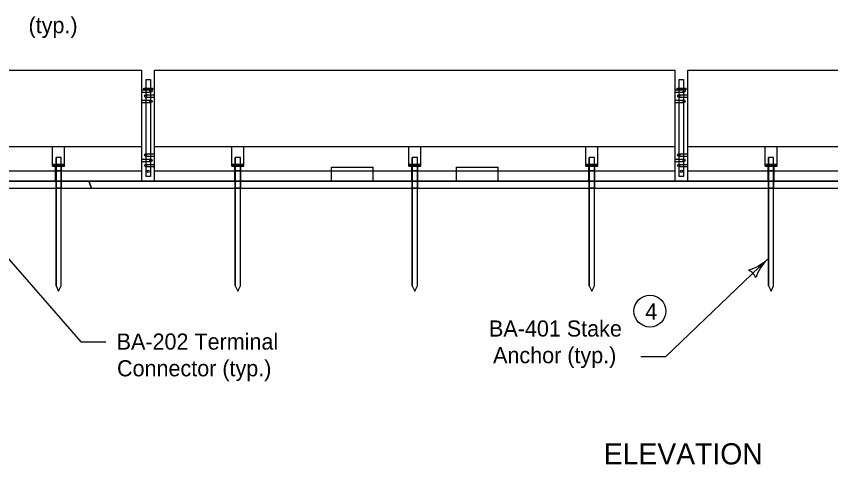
# Model space of a CAD drawing. Extents: x -2137026 to -2131464, y -2138478 to -2136524.
# Drawn here: x -2136307 to -2135538, y -2138383 to -2137959 of the extents above; entities that cross this region are included whole.
import ezdxf

# ---------------------------------------------------------------- set-up
doc = ezdxf.new("R2010")
doc.units = 0
for name, color, linetype in [('conPaving', 7, 'Continuous'), ('Level 2', 7, 'Continuous'), ('Level 3', 7, 'Continuous'), ('Level 41', 7, 'Continuous'), ('Level 9', 7, 'Continuous')]:
    doc.layers.add(name, color=color, linetype=linetype)

msp = doc.modelspace()

# ---------------------------------------------------------------- linework, layer by layer
at = {"layer": 'conPaving'}
for p, q in [((-2136269.98, -2138114.82), (-2136355.62, -2138114.82)), ((-2136269.6, -2138114.82), (-2136269.98, -2138114.82)), ((-2136269.6, -2138121.37), (-2136269.6, -2138114.82)), ((-2136264.69, -2138114.82), (-2136264.69, -2138121.37)), ((-2136188.75, -2138114.82), (-2136238.46, -2138114.82)), ((-2136238.46, -2138114.82), (-2136236.14, -2138121.37)), ((-2136236.14, -2138121.37), (-2136238.46, -2138114.82)), ((-2136176.38, -2138114.82), (-2136188.75, -2138114.82)), ((-2136100.81, -2138114.82), (-2136176.38, -2138114.82)), ((-2136100.44, -2138114.82), (-2136100.81, -2138114.82)), ((-2136100.44, -2138121.37), (-2136100.44, -2138114.82)), ((-2136095.52, -2138114.82), (-2136095.52, -2138121.37)), ((-2135970.18, -2138114.82), (-2136009.51, -2138114.82)), ((-2135933.32, -2138121.37), (-2135933.32, -2138114.82)), ((-2135928.41, -2138114.82), (-2135928.41, -2138121.37)), ((-2135766.2, -2138114.82), (-2135766.58, -2138114.82)), ((-2135766.2, -2138121.37), (-2135766.2, -2138114.82)), ((-2135760.92, -2138114.82), (-2135761.29, -2138114.82)), ((-2135761.29, -2138114.82), (-2135761.29, -2138121.37)), ((-2135685.35, -2138114.82), (-2135760.92, -2138114.82)), ((-2135597.04, -2138114.82), (-2135597.41, -2138114.82)), ((-2135597.04, -2138121.37), (-2135597.04, -2138114.82)), ((-2135592.12, -2138114.82), (-2135592.12, -2138121.37)), ((-2136431.8, -2138121.37), (-2136269.6, -2138121.37)), ((-2136264.69, -2138121.37), (-2136236.14, -2138121.37)), ((-2136236.14, -2138121.37), (-2136100.44, -2138121.37)), ((-2136095.52, -2138121.37), (-2135933.32, -2138121.37)), ((-2135928.41, -2138121.37), (-2135766.2, -2138121.37)), ((-2135761.29, -2138121.37), (-2135597.04, -2138121.37)), ((-2135592.12, -2138121.37), (-2135530.9, -2138121.37))]:
    msp.add_line(p, q, dxfattribs=at)
for points in [[(-2136238.46, -2138114.82), (-2136264.31, -2138114.82), (-2136264.69, -2138114.82)], [(-2136009.51, -2138114.82), (-2136095.15, -2138114.82), (-2136095.52, -2138114.82)], [(-2135933.32, -2138114.82), (-2135933.69, -2138114.82), (-2135970.18, -2138114.82)], [(-2135766.58, -2138114.82), (-2135852.22, -2138114.82), (-2135891.54, -2138114.82), (-2135928.03, -2138114.82), (-2135928.41, -2138114.82)], [(-2135597.41, -2138114.82), (-2135672.98, -2138114.82), (-2135685.35, -2138114.82)], [(-2135430.3, -2138114.82), (-2135466.79, -2138114.82), (-2135506.11, -2138114.82), (-2135591.75, -2138114.82), (-2135592.12, -2138114.82)]]:
    msp.add_lwpolyline(points, dxfattribs=at)
at = {"layer": 'Level 2'}
for p, q in [((-2136680.02, -2138009.96), (-2136188.5, -2138009.96)), ((-2136188.5, -2138114.57), (-2136188.5, -2138009.96)), ((-2136176.62, -2138114.57), (-2136176.62, -2138009.96)), ((-2136176.62, -2138009.96), (-2135685.1, -2138009.96)), ((-2135685.1, -2138114.57), (-2135685.1, -2138009.96)), ((-2135673.22, -2138114.57), (-2135673.22, -2138009.96)), ((-2135673.22, -2138009.96), (-2135181.7, -2138009.96)), ((-2136410.46, -2138078.28), (-2136246.26, -2138266.62)), ((-2136680.02, -2138082.05), (-2136188.5, -2138082.05)), ((-2136176.62, -2138082.05), (-2135685.1, -2138082.05)), ((-2135673.22, -2138082.05), (-2135181.7, -2138082.05)), ((-2136009.51, -2138101.71), (-2135970.18, -2138101.71)), ((-2135891.54, -2138101.71), (-2135852.22, -2138101.71)), ((-2136680.02, -2138104.99), (-2136188.5, -2138104.99)), ((-2136176.62, -2138104.99), (-2135685.1, -2138104.99)), ((-2136009.51, -2138114.82), (-2136009.51, -2138104.99)), ((-2135970.18, -2138114.82), (-2135970.18, -2138104.99)), ((-2135891.54, -2138114.82), (-2135891.54, -2138104.99)), ((-2135852.22, -2138114.82), (-2135852.22, -2138104.99)), ((-2135673.22, -2138104.99), (-2135181.7, -2138104.99)), ((-2136355.62, -2138114.82), (-2136188.75, -2138114.82)), ((-2136176.38, -2138114.82), (-2136009.51, -2138114.82)), ((-2135970.18, -2138114.82), (-2135891.54, -2138114.82)), ((-2135852.22, -2138114.82), (-2135685.35, -2138114.82)), ((-2135672.98, -2138114.82), (-2135506.11, -2138114.82)), ((-2135693.85, -2138280.43), (-2135598, -2138188.49)), ((-2136246.26, -2138266.62), (-2136222.65, -2138266.62)), ((-2135717.45, -2138280.43), (-2135693.85, -2138280.43))]:
    msp.add_line(p, q, dxfattribs=at)
msp.add_circle((-2135708.96, -2138237.57), 15, dxfattribs=at)
for centre, radius, start, end in [((-2135627.42, -2138157.82), 42.5, 285.73709, 313.80957), ((-2135568.58, -2138219.16), 42.5, 133.80957, 161.88206), ((-2135623.71, -2138213.16), 16.42, 26.07622, 61.54292)]:
    msp.add_arc(centre, radius, start, end, dxfattribs=at)
at = {"layer": 'Level 41'}
for p, q in [((-2136188.5, -2138028.56), (-2136180, -2138028.56)), ((-2136188.5, -2138030.68), (-2136180, -2138030.68)), ((-2136185.13, -2138033.48), (-2136176.62, -2138033.48)), ((-2135685.1, -2138028.56), (-2135676.6, -2138028.56)), ((-2135685.1, -2138030.68), (-2135676.6, -2138030.68)), ((-2135681.73, -2138033.48), (-2135673.22, -2138033.48)), ((-2136188.49, -2138038.39), (-2136180, -2138038.39)), ((-2136188.49, -2138040.51), (-2136180, -2138040.51)), ((-2136185.13, -2138035.6), (-2136176.62, -2138035.6)), ((-2135685.09, -2138038.39), (-2135676.6, -2138038.39)), ((-2135685.09, -2138040.51), (-2135676.6, -2138040.51)), ((-2135681.73, -2138035.6), (-2135673.22, -2138035.6)), ((-2136272.81, -2138100.62), (-2136272.81, -2138082.05)), ((-2136261.48, -2138100.62), (-2136261.48, -2138082.05)), ((-2136103.64, -2138100.62), (-2136103.64, -2138082.05)), ((-2136092.32, -2138100.62), (-2136092.32, -2138082.05)), ((-2135936.53, -2138100.62), (-2135936.53, -2138082.05)), ((-2135925.2, -2138100.62), (-2135925.2, -2138082.05)), ((-2135769.41, -2138100.62), (-2135769.41, -2138082.05)), ((-2135758.08, -2138100.62), (-2135758.08, -2138082.05)), ((-2135600.24, -2138100.62), (-2135600.24, -2138082.05)), ((-2135588.92, -2138100.62), (-2135588.92, -2138082.05)), ((-2136188.5, -2138094.1), (-2136180.01, -2138094.1)), ((-2136188.5, -2138096.22), (-2136180.01, -2138096.22)), ((-2136185.13, -2138089.18), (-2136176.63, -2138089.18)), ((-2136185.13, -2138091.31), (-2136176.63, -2138091.31)), ((-2135685.1, -2138094.1), (-2135676.61, -2138094.1)), ((-2135685.1, -2138096.22), (-2135676.61, -2138096.22)), ((-2135681.73, -2138089.18), (-2135673.23, -2138089.18)), ((-2135681.73, -2138091.31), (-2135673.23, -2138091.31)), ((-2136272.81, -2138100.62), (-2136261.48, -2138100.62)), ((-2136269.98, -2138114.82), (-2136269.98, -2138100.62)), ((-2136264.31, -2138114.82), (-2136264.31, -2138100.62)), ((-2136185.13, -2138099.01), (-2136176.63, -2138099.01)), ((-2136185.13, -2138101.14), (-2136176.63, -2138101.14)), ((-2136103.64, -2138100.62), (-2136092.32, -2138100.62)), ((-2136100.81, -2138114.82), (-2136100.81, -2138100.62)), ((-2136095.15, -2138114.82), (-2136095.15, -2138100.62)), ((-2135936.53, -2138100.62), (-2135925.2, -2138100.62)), ((-2135933.69, -2138114.82), (-2135933.69, -2138100.62)), ((-2135928.03, -2138114.82), (-2135928.03, -2138100.62)), ((-2135769.41, -2138100.62), (-2135758.08, -2138100.62)), ((-2135766.58, -2138114.82), (-2135766.58, -2138100.62)), ((-2135760.92, -2138114.82), (-2135760.92, -2138100.62)), ((-2135681.73, -2138099.01), (-2135673.23, -2138099.01)), ((-2135681.73, -2138101.14), (-2135673.23, -2138101.14)), ((-2135600.24, -2138100.62), (-2135588.92, -2138100.62)), ((-2135597.41, -2138114.82), (-2135597.41, -2138100.62)), ((-2135591.75, -2138114.82), (-2135591.75, -2138100.62))]:
    msp.add_line(p, q, dxfattribs=at)
for centre in [(-2136185.13, -2138034.54), (-2136180, -2138029.62), (-2135681.73, -2138034.54), (-2135676.6, -2138029.62), (-2136180, -2138039.45), (-2135676.6, -2138039.45), (-2136185.13, -2138090.24), (-2136180, -2138095.16), (-2135681.73, -2138090.24), (-2135676.6, -2138095.16), (-2136185.13, -2138100.07), (-2135681.73, -2138100.07)]:
    msp.add_circle(centre, 1.06, dxfattribs=at)
at = {"layer": 'Level 9'}
for p, q in [((-2136184.61, -2138018.73), (-2136180.51, -2138018.73)), ((-2136184.61, -2138026.92), (-2136184.61, -2138018.73)), ((-2136180.51, -2138018.73), (-2136180.51, -2138026.92)), ((-2135681.21, -2138018.73), (-2135677.12, -2138018.73)), ((-2135681.21, -2138026.92), (-2135681.21, -2138018.73)), ((-2135677.12, -2138018.73), (-2135677.12, -2138026.92)), ((-2136186.66, -2138026.92), (-2136178.47, -2138026.92)), ((-2136186.66, -2138028.56), (-2136186.66, -2138026.92)), ((-2136178.47, -2138026.92), (-2136178.47, -2138028.56)), ((-2135683.26, -2138026.92), (-2135675.07, -2138026.92)), ((-2135683.26, -2138028.56), (-2135683.26, -2138026.92)), ((-2135675.07, -2138026.92), (-2135675.07, -2138028.56)), ((-2136178.47, -2138028.56), (-2136186.66, -2138028.56)), ((-2136184.61, -2138110.48), (-2136184.61, -2138028.56)), ((-2136180.51, -2138028.56), (-2136180.51, -2138110.48)), ((-2135675.07, -2138028.56), (-2135683.26, -2138028.56)), ((-2135681.21, -2138110.48), (-2135681.21, -2138028.56)), ((-2135677.12, -2138028.56), (-2135677.12, -2138110.48)), ((-2136264.69, -2138092.42), (-2136269.6, -2138092.42)), ((-2136269.6, -2138092.42), (-2136269.6, -2138098.98)), ((-2136264.69, -2138092.42), (-2136269.6, -2138092.42)), ((-2136269.6, -2138213.67), (-2136269.6, -2138092.42)), ((-2136264.69, -2138098.98), (-2136264.69, -2138092.42)), ((-2136264.69, -2138213.67), (-2136264.69, -2138092.42)), ((-2136095.52, -2138092.42), (-2136100.44, -2138092.42)), ((-2136100.44, -2138092.42), (-2136100.44, -2138098.98)), ((-2136095.52, -2138092.42), (-2136100.44, -2138092.42)), ((-2136100.44, -2138213.67), (-2136100.44, -2138092.42)), ((-2136095.52, -2138098.98), (-2136095.52, -2138092.42)), ((-2136095.52, -2138213.67), (-2136095.52, -2138092.42)), ((-2135928.41, -2138092.42), (-2135933.32, -2138092.42)), ((-2135933.32, -2138092.42), (-2135933.32, -2138098.98)), ((-2135928.41, -2138092.42), (-2135933.32, -2138092.42)), ((-2135933.32, -2138213.67), (-2135933.32, -2138092.42)), ((-2135928.41, -2138098.98), (-2135928.41, -2138092.42)), ((-2135928.41, -2138213.67), (-2135928.41, -2138092.42)), ((-2135761.29, -2138092.42), (-2135766.2, -2138092.42)), ((-2135766.2, -2138092.42), (-2135766.2, -2138098.98)), ((-2135761.29, -2138092.42), (-2135766.2, -2138092.42)), ((-2135766.2, -2138213.67), (-2135766.2, -2138092.42)), ((-2135761.29, -2138098.98), (-2135761.29, -2138092.42)), ((-2135761.29, -2138213.67), (-2135761.29, -2138092.42)), ((-2135592.12, -2138092.42), (-2135597.04, -2138092.42)), ((-2135597.04, -2138092.42), (-2135597.04, -2138098.98)), ((-2135592.12, -2138092.42), (-2135597.04, -2138092.42)), ((-2135597.04, -2138213.67), (-2135597.04, -2138092.42)), ((-2135592.12, -2138098.98), (-2135592.12, -2138092.42)), ((-2135592.12, -2138213.67), (-2135592.12, -2138092.42)), ((-2136272.06, -2138098.98), (-2136272.06, -2138100.62)), ((-2136269.6, -2138098.98), (-2136272.06, -2138098.98)), ((-2136272.06, -2138100.62), (-2136272.06, -2138098.98)), ((-2136272.06, -2138100.62), (-2136269.98, -2138100.62)), ((-2136269.98, -2138100.62), (-2136269.6, -2138100.62)), ((-2136264.69, -2138098.98), (-2136269.6, -2138098.98)), ((-2136269.6, -2138098.98), (-2136269.6, -2138100.62)), ((-2136269.6, -2138100.62), (-2136269.6, -2138098.98)), ((-2136269.6, -2138098.98), (-2136264.69, -2138098.98)), ((-2136264.69, -2138100.62), (-2136269.6, -2138100.62)), ((-2136269.6, -2138100.62), (-2136269.6, -2138104.99)), ((-2136269.6, -2138100.62), (-2136264.69, -2138100.62)), ((-2136264.69, -2138100.62), (-2136264.69, -2138098.98)), ((-2136264.69, -2138098.98), (-2136264.69, -2138100.62)), ((-2136264.69, -2138104.99), (-2136264.69, -2138100.62)), ((-2136102.9, -2138098.98), (-2136102.9, -2138100.62)), ((-2136100.44, -2138098.98), (-2136102.9, -2138098.98)), ((-2136102.9, -2138100.62), (-2136102.9, -2138098.98)), ((-2136102.9, -2138100.62), (-2136100.81, -2138100.62)), ((-2136100.81, -2138100.62), (-2136100.44, -2138100.62)), ((-2136095.52, -2138098.98), (-2136100.44, -2138098.98)), ((-2136100.44, -2138098.98), (-2136100.44, -2138100.62)), ((-2136100.44, -2138100.62), (-2136100.44, -2138098.98)), ((-2136100.44, -2138098.98), (-2136095.52, -2138098.98)), ((-2136095.52, -2138100.62), (-2136100.44, -2138100.62)), ((-2136100.44, -2138100.62), (-2136100.44, -2138104.99)), ((-2136100.44, -2138100.62), (-2136095.52, -2138100.62)), ((-2136095.52, -2138100.62), (-2136095.52, -2138098.98)), ((-2136095.52, -2138098.98), (-2136095.52, -2138100.62)), ((-2136095.52, -2138104.99), (-2136095.52, -2138100.62)), ((-2136009.51, -2138104.99), (-2136009.51, -2138101.71)), ((-2135970.18, -2138104.99), (-2135970.18, -2138101.71)), ((-2135935.78, -2138098.98), (-2135935.78, -2138100.62)), ((-2135933.32, -2138098.98), (-2135935.78, -2138098.98)), ((-2135935.78, -2138100.62), (-2135935.78, -2138098.98)), ((-2135935.78, -2138100.62), (-2135933.69, -2138100.62)), ((-2135933.69, -2138100.62), (-2135933.32, -2138100.62)), ((-2135928.41, -2138098.98), (-2135933.32, -2138098.98)), ((-2135933.32, -2138098.98), (-2135933.32, -2138100.62)), ((-2135933.32, -2138100.62), (-2135933.32, -2138098.98)), ((-2135933.32, -2138098.98), (-2135928.41, -2138098.98)), ((-2135928.41, -2138100.62), (-2135933.32, -2138100.62)), ((-2135933.32, -2138100.62), (-2135933.32, -2138104.99)), ((-2135933.32, -2138100.62), (-2135928.41, -2138100.62)), ((-2135928.41, -2138100.62), (-2135928.41, -2138098.98)), ((-2135928.41, -2138098.98), (-2135928.41, -2138100.62)), ((-2135928.41, -2138104.99), (-2135928.41, -2138100.62)), ((-2135891.54, -2138104.99), (-2135891.54, -2138101.71)), ((-2135852.22, -2138104.99), (-2135852.22, -2138101.71)), ((-2135768.66, -2138098.98), (-2135768.66, -2138100.62)), ((-2135766.2, -2138098.98), (-2135768.66, -2138098.98)), ((-2135768.66, -2138100.62), (-2135768.66, -2138098.98)), ((-2135768.66, -2138100.62), (-2135766.58, -2138100.62)), ((-2135766.58, -2138100.62), (-2135766.2, -2138100.62)), ((-2135761.29, -2138098.98), (-2135766.2, -2138098.98)), ((-2135766.2, -2138098.98), (-2135766.2, -2138100.62)), ((-2135766.2, -2138100.62), (-2135766.2, -2138098.98)), ((-2135766.2, -2138098.98), (-2135761.29, -2138098.98)), ((-2135761.29, -2138100.62), (-2135766.2, -2138100.62)), ((-2135766.2, -2138100.62), (-2135766.2, -2138104.99)), ((-2135766.2, -2138100.62), (-2135761.29, -2138100.62)), ((-2135761.29, -2138100.62), (-2135761.29, -2138098.98)), ((-2135761.29, -2138098.98), (-2135761.29, -2138100.62)), ((-2135761.29, -2138104.99), (-2135761.29, -2138100.62)), ((-2135599.5, -2138098.98), (-2135599.5, -2138100.62)), ((-2135597.04, -2138098.98), (-2135599.5, -2138098.98)), ((-2135599.5, -2138100.62), (-2135599.5, -2138098.98)), ((-2135599.5, -2138100.62), (-2135597.41, -2138100.62)), ((-2135597.41, -2138100.62), (-2135597.04, -2138100.62)), ((-2135592.12, -2138098.98), (-2135597.04, -2138098.98)), ((-2135597.04, -2138098.98), (-2135597.04, -2138100.62)), ((-2135597.04, -2138100.62), (-2135597.04, -2138098.98)), ((-2135597.04, -2138098.98), (-2135592.12, -2138098.98)), ((-2135592.12, -2138100.62), (-2135597.04, -2138100.62)), ((-2135597.04, -2138100.62), (-2135597.04, -2138104.99)), ((-2135597.04, -2138100.62), (-2135592.12, -2138100.62)), ((-2135592.12, -2138100.62), (-2135592.12, -2138098.98)), ((-2135592.12, -2138098.98), (-2135592.12, -2138100.62)), ((-2135592.12, -2138104.99), (-2135592.12, -2138100.62)), ((-2136264.69, -2138104.99), (-2136269.6, -2138104.99)), ((-2136269.6, -2138104.99), (-2136269.6, -2138114.82)), ((-2136269.6, -2138104.99), (-2136264.69, -2138104.99)), ((-2136264.69, -2138114.82), (-2136264.69, -2138104.99)), ((-2136180.51, -2138110.48), (-2136184.61, -2138110.48)), ((-2136095.52, -2138104.99), (-2136100.44, -2138104.99)), ((-2136100.44, -2138104.99), (-2136100.44, -2138114.82)), ((-2136100.44, -2138104.99), (-2136095.52, -2138104.99)), ((-2136095.52, -2138114.82), (-2136095.52, -2138104.99)), ((-2136009.51, -2138104.99), (-2135970.18, -2138104.99)), ((-2135928.41, -2138104.99), (-2135933.32, -2138104.99)), ((-2135933.32, -2138104.99), (-2135933.32, -2138114.82)), ((-2135933.32, -2138104.99), (-2135928.41, -2138104.99)), ((-2135928.41, -2138114.82), (-2135928.41, -2138104.99)), ((-2135891.54, -2138104.99), (-2135852.22, -2138104.99)), ((-2135761.29, -2138104.99), (-2135766.2, -2138104.99)), ((-2135766.2, -2138104.99), (-2135766.2, -2138114.82)), ((-2135766.2, -2138104.99), (-2135761.29, -2138104.99)), ((-2135761.29, -2138114.82), (-2135761.29, -2138104.99)), ((-2135677.12, -2138110.48), (-2135681.21, -2138110.48)), ((-2135592.12, -2138104.99), (-2135597.04, -2138104.99)), ((-2135597.04, -2138104.99), (-2135597.04, -2138114.82)), ((-2135597.04, -2138104.99), (-2135592.12, -2138104.99)), ((-2135592.12, -2138114.82), (-2135592.12, -2138104.99)), ((-2136987.54, -2138114.82), (-2134196.38, -2138114.82)), ((-2136264.69, -2138114.82), (-2136269.6, -2138114.82)), ((-2136269.6, -2138114.82), (-2136269.6, -2138121.37)), ((-2136269.6, -2138114.82), (-2136264.69, -2138114.82)), ((-2136264.69, -2138121.37), (-2136264.69, -2138114.82)), ((-2136188.75, -2138114.82), (-2136188.5, -2138114.57)), ((-2136176.62, -2138114.57), (-2136176.38, -2138114.82)), ((-2136095.52, -2138114.82), (-2136100.44, -2138114.82)), ((-2136100.44, -2138114.82), (-2136100.44, -2138121.37)), ((-2136100.44, -2138114.82), (-2136095.52, -2138114.82)), ((-2136095.52, -2138121.37), (-2136095.52, -2138114.82)), ((-2135928.41, -2138114.82), (-2135933.32, -2138114.82)), ((-2135933.32, -2138114.82), (-2135933.32, -2138121.37)), ((-2135933.32, -2138114.82), (-2135928.41, -2138114.82)), ((-2135928.41, -2138121.37), (-2135928.41, -2138114.82)), ((-2135761.29, -2138114.82), (-2135766.2, -2138114.82)), ((-2135766.2, -2138114.82), (-2135766.2, -2138121.37)), ((-2135766.2, -2138114.82), (-2135761.29, -2138114.82)), ((-2135761.29, -2138121.37), (-2135761.29, -2138114.82)), ((-2135685.35, -2138114.82), (-2135685.1, -2138114.57)), ((-2135673.22, -2138114.57), (-2135672.98, -2138114.82)), ((-2135592.12, -2138114.82), (-2135597.04, -2138114.82)), ((-2135597.04, -2138114.82), (-2135597.04, -2138121.37)), ((-2135597.04, -2138114.82), (-2135592.12, -2138114.82)), ((-2135592.12, -2138121.37), (-2135592.12, -2138114.82)), ((-2136691.9, -2138121.37), (-2134672.37, -2138121.37)), ((-2136264.69, -2138121.37), (-2136269.6, -2138121.37)), ((-2136269.6, -2138121.37), (-2136269.6, -2138213.67)), ((-2136269.6, -2138121.37), (-2136264.69, -2138121.37)), ((-2136264.69, -2138213.67), (-2136264.69, -2138121.37)), ((-2136095.52, -2138121.37), (-2136100.44, -2138121.37)), ((-2136100.44, -2138121.37), (-2136100.44, -2138213.67)), ((-2136100.44, -2138121.37), (-2136095.52, -2138121.37)), ((-2136095.52, -2138213.67), (-2136095.52, -2138121.37)), ((-2135928.41, -2138121.37), (-2135933.32, -2138121.37)), ((-2135933.32, -2138121.37), (-2135933.32, -2138213.67)), ((-2135933.32, -2138121.37), (-2135928.41, -2138121.37)), ((-2135928.41, -2138213.67), (-2135928.41, -2138121.37)), ((-2135761.29, -2138121.37), (-2135766.2, -2138121.37)), ((-2135766.2, -2138121.37), (-2135766.2, -2138213.67)), ((-2135766.2, -2138121.37), (-2135761.29, -2138121.37)), ((-2135761.29, -2138213.67), (-2135761.29, -2138121.37)), ((-2135592.12, -2138121.37), (-2135597.04, -2138121.37)), ((-2135597.04, -2138121.37), (-2135597.04, -2138213.67)), ((-2135597.04, -2138121.37), (-2135592.12, -2138121.37)), ((-2135592.12, -2138213.67), (-2135592.12, -2138121.37)), ((-2136269.6, -2138213.67), (-2136267.14, -2138218.58)), ((-2136269.6, -2138213.67), (-2136267.14, -2138218.58)), ((-2136267.14, -2138218.58), (-2136264.69, -2138213.67)), ((-2136267.14, -2138218.58), (-2136264.69, -2138213.67)), ((-2136100.44, -2138213.67), (-2136097.98, -2138218.58)), ((-2136100.44, -2138213.67), (-2136097.98, -2138218.58)), ((-2136097.98, -2138218.58), (-2136095.52, -2138213.67)), ((-2136097.98, -2138218.58), (-2136095.52, -2138213.67)), ((-2135933.32, -2138213.67), (-2135930.86, -2138218.58)), ((-2135933.32, -2138213.67), (-2135930.86, -2138218.58)), ((-2135930.86, -2138218.58), (-2135928.41, -2138213.67)), ((-2135930.86, -2138218.58), (-2135928.41, -2138213.67)), ((-2135766.2, -2138213.67), (-2135763.75, -2138218.58)), ((-2135766.2, -2138213.67), (-2135763.75, -2138218.58)), ((-2135763.75, -2138218.58), (-2135761.29, -2138213.67)), ((-2135763.75, -2138218.58), (-2135761.29, -2138213.67)), ((-2135597.04, -2138213.67), (-2135594.58, -2138218.58)), ((-2135597.04, -2138213.67), (-2135594.58, -2138218.58)), ((-2135594.58, -2138218.58), (-2135592.12, -2138213.67)), ((-2135594.58, -2138218.58), (-2135592.12, -2138213.67))]:
    msp.add_line(p, q, dxfattribs=at)
for points in [[(-2136272.06, -2138098.98), (-2136262.23, -2138098.98), (-2136262.23, -2138100.62), (-2136272.06, -2138100.62)], [(-2136262.23, -2138100.62), (-2136262.23, -2138098.98), (-2136264.69, -2138098.98)], [(-2136264.69, -2138100.62), (-2136264.31, -2138100.62), (-2136262.23, -2138100.62)], [(-2136102.9, -2138098.98), (-2136093.06, -2138098.98), (-2136093.06, -2138100.62), (-2136102.9, -2138100.62)], [(-2136093.06, -2138100.62), (-2136093.06, -2138098.98), (-2136095.52, -2138098.98)], [(-2136095.52, -2138100.62), (-2136095.15, -2138100.62), (-2136093.06, -2138100.62)], [(-2135935.78, -2138098.98), (-2135925.95, -2138098.98), (-2135925.95, -2138100.62), (-2135935.78, -2138100.62)], [(-2135925.95, -2138100.62), (-2135925.95, -2138098.98), (-2135928.41, -2138098.98)], [(-2135928.41, -2138100.62), (-2135928.03, -2138100.62), (-2135925.95, -2138100.62)], [(-2135768.66, -2138098.98), (-2135758.83, -2138098.98), (-2135758.83, -2138100.62), (-2135768.66, -2138100.62)], [(-2135758.83, -2138100.62), (-2135758.83, -2138098.98), (-2135761.29, -2138098.98)], [(-2135761.29, -2138100.62), (-2135760.92, -2138100.62), (-2135758.83, -2138100.62)], [(-2135599.5, -2138098.98), (-2135589.67, -2138098.98), (-2135589.67, -2138100.62), (-2135599.5, -2138100.62)], [(-2135589.67, -2138100.62), (-2135589.67, -2138098.98), (-2135592.12, -2138098.98)], [(-2135592.12, -2138100.62), (-2135591.75, -2138100.62), (-2135589.67, -2138100.62)]]:
    msp.add_lwpolyline(points, dxfattribs=at)
for centre in [(-2136182.56, -2138105.57), (-2135679.16, -2138105.57)]:
    msp.add_circle(centre, 1.02, dxfattribs=at)

# ---------------------------------------------------------------- texts
at = {"layer": 'Level 2'}
msp.add_text('4', height=15.2, dxfattribs=at).set_placement((-2135713.33, -2138245.48))
at = {"layer": 'Level 3'}
for s, height, p in [('(typ.)', 15.2, (-2136295.52, -2137975.2)), ('BA-401 Stake', 15.2, (-2135860.81, -2138261.57)), ('BA-202 Terminal', 15.2, (-2136212.34, -2138273.92)), ('Anchor (typ.)', 15.2, (-2135856.98, -2138286.77)), ('Connector (typ.)', 15.2, (-2136212, -2138299.12)), ('ELEVATION', 20, (-2135752.5, -2138382.29))]:
    msp.add_text(s, height=height, dxfattribs=at).set_placement(p)

doc.saveas('drawing.dxf')
